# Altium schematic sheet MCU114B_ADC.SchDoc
size 431 x 279 mm; Date: Not shown in title block; ApprovedBy: Not shown in title block; CheckedBy: Not shown in title block; Author: Not shown in title block; CompanyName: Not shown in title block; Engineer: Not shown in title block; Organization: Not shown in title block; Address1: Not shown in title block; Address2: Not shown in title block; Address3: Not shown in title block; Address4: Not shown in title block; DocumentNumber: 4; Revision: Use project parameter SCH_Rev; SheetNumber: 4; SheetTotal: 11; PageSetup: Record=PageOptions¦CenterHorizontal=True¦CenterVertical=True¦PrintScale=1.00¦XCorrection=1.00¦YCorrection=1.00¦PrintKind=0¦BorderSize=5000000¦LeftOffset=0¦BottomOffset=0¦Orientation=2¦PaperLength=1000¦PaperWidth=1000¦Scale=100¦PaperSource=15¦PrintQuality=600¦MediaType=1¦DitherType=10¦PaperKind=Letter¦PrintScaleMode=1
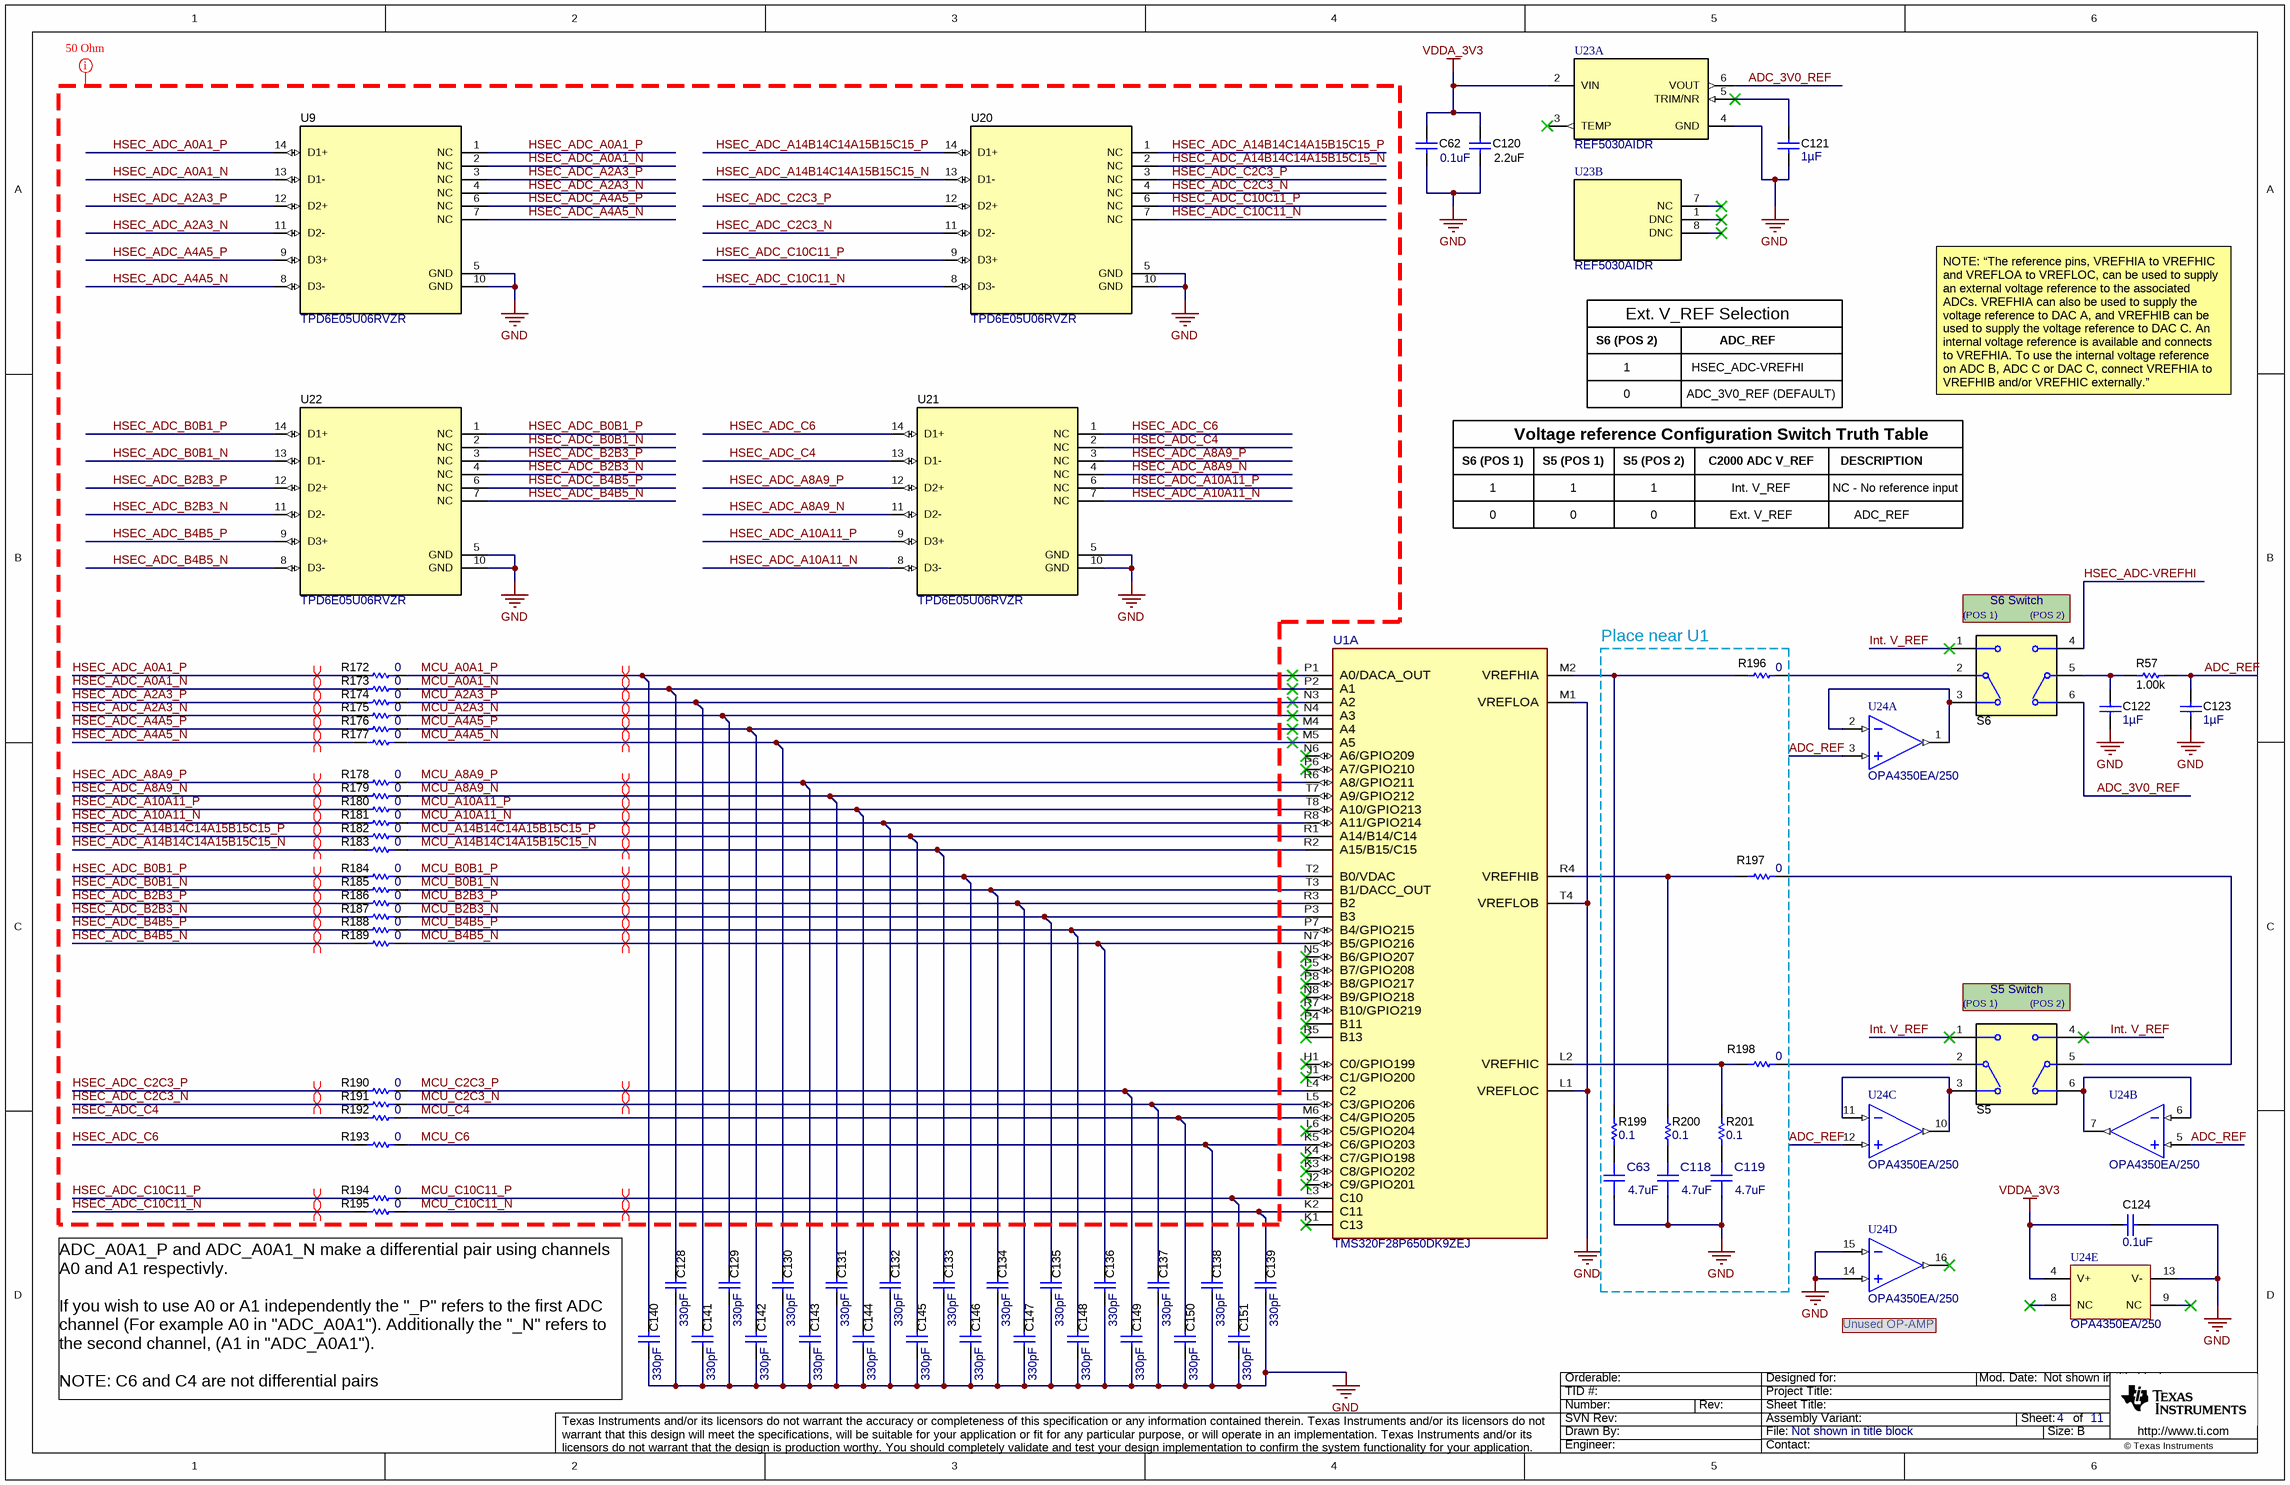
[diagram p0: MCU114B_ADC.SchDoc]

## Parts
C62  Cap_F: 0.1uF  [0603]  (hidden comment: 885012206046)
C63  ValueDisplayed: 4.7uF  [FP-885012106012_0603-MFG]  (hidden comment: 885012106012)
C118  ValueDisplayed: 4.7uF  [FP-885012106012_0603-MFG]  (hidden comment: 885012106012)
C119  ValueDisplayed: 4.7uF  [FP-885012106012_0603-MFG]  (hidden comment: 885012106012)
C120  ValueDisplayed: 2.2uF  [0603]  (hidden comment: 885012106018)
C121  Cap_F: 1µF  [0603]  (hidden comment: 885012206052)
C122  Cap_F: 1µF  [0603]  (hidden comment: 885012206052)
C123  Cap_F: 1µF  [0603]  (hidden comment: 885012206052)
C124  Cap_F: 0.1uF  [0603]  (hidden comment: 885012206046)
C128  ValueDisplayed: 330pF  [0603]  (hidden comment: C0603C331J5GACTU)
C129  ValueDisplayed: 330pF  [0603]  (hidden comment: C0603C331J5GACTU)
C130  ValueDisplayed: 330pF  [0603]  (hidden comment: C0603C331J5GACTU)
C131  ValueDisplayed: 330pF  [0603]  (hidden comment: C0603C331J5GACTU)
C132  ValueDisplayed: 330pF  [0603]  (hidden comment: C0603C331J5GACTU)
C133  ValueDisplayed: 330pF  [0603]  (hidden comment: C0603C331J5GACTU)
C134  ValueDisplayed: 330pF  [0603]  (hidden comment: C0603C331J5GACTU)
C135  ValueDisplayed: 330pF  [0603]  (hidden comment: C0603C331J5GACTU)
C136  ValueDisplayed: 330pF  [0603]  (hidden comment: C0603C331J5GACTU)
C137  ValueDisplayed: 330pF  [0603]  (hidden comment: C0603C331J5GACTU)
C138  ValueDisplayed: 330pF  [0603]  (hidden comment: C0603C331J5GACTU)
C139  ValueDisplayed: 330pF  [0603]  (hidden comment: C0603C331J5GACTU)
C140  ValueDisplayed: 330pF  [0603]  (hidden comment: C0603C331J5GACTU)
C141  ValueDisplayed: 330pF  [0603]  (hidden comment: C0603C331J5GACTU)
C142  ValueDisplayed: 330pF  [0603]  (hidden comment: C0603C331J5GACTU)
C143  ValueDisplayed: 330pF  [0603]  (hidden comment: C0603C331J5GACTU)
C144  ValueDisplayed: 330pF  [0603]  (hidden comment: C0603C331J5GACTU)
C145  ValueDisplayed: 330pF  [0603]  (hidden comment: C0603C331J5GACTU)
C146  ValueDisplayed: 330pF  [0603]  (hidden comment: C0603C331J5GACTU)
C147  ValueDisplayed: 330pF  [0603]  (hidden comment: C0603C331J5GACTU)
C148  ValueDisplayed: 330pF  [0603]  (hidden comment: C0603C331J5GACTU)
C149  ValueDisplayed: 330pF  [0603]  (hidden comment: C0603C331J5GACTU)
C150  ValueDisplayed: 330pF  [0603]  (hidden comment: C0603C331J5GACTU)
C151  ValueDisplayed: 330pF  [0603]  (hidden comment: C0603C331J5GACTU)
R57  ValueDisplayed: 1.00k  [0603]  (hidden comment: RC0603FR-071KL)
R172  ValueDisplayed: 0  [0603]  (hidden comment: ERJ-3GEY0R00V)
R173  ValueDisplayed: 0  [0603]  (hidden comment: ERJ-3GEY0R00V)
R174  ValueDisplayed: 0  [0603]  (hidden comment: ERJ-3GEY0R00V)
R175  ValueDisplayed: 0  [0603]  (hidden comment: ERJ-3GEY0R00V)
R176  ValueDisplayed: 0  [0603]  (hidden comment: ERJ-3GEY0R00V)
R177  ValueDisplayed: 0  [0603]  (hidden comment: ERJ-3GEY0R00V)
R178  ValueDisplayed: 0  [0603]  (hidden comment: ERJ-3GEY0R00V)
R179  ValueDisplayed: 0  [0603]  (hidden comment: ERJ-3GEY0R00V)
R180  ValueDisplayed: 0  [0603]  (hidden comment: ERJ-3GEY0R00V)
R181  ValueDisplayed: 0  [0603]  (hidden comment: ERJ-3GEY0R00V)
R182  ValueDisplayed: 0  [0603]  (hidden comment: ERJ-3GEY0R00V)
R183  ValueDisplayed: 0  [0603]  (hidden comment: ERJ-3GEY0R00V)
R184  ValueDisplayed: 0  [0603]  (hidden comment: ERJ-3GEY0R00V)
R185  ValueDisplayed: 0  [0603]  (hidden comment: ERJ-3GEY0R00V)
R186  ValueDisplayed: 0  [0603]  (hidden comment: ERJ-3GEY0R00V)
R187  ValueDisplayed: 0  [0603]  (hidden comment: ERJ-3GEY0R00V)
R188  ValueDisplayed: 0  [0603]  (hidden comment: ERJ-3GEY0R00V)
R189  ValueDisplayed: 0  [0603]  (hidden comment: ERJ-3GEY0R00V)
R190  ValueDisplayed: 0  [0603]  (hidden comment: ERJ-3GEY0R00V)
R191  ValueDisplayed: 0  [0603]  (hidden comment: ERJ-3GEY0R00V)
R192  ValueDisplayed: 0  [0603]  (hidden comment: ERJ-3GEY0R00V)
R193  ValueDisplayed: 0  [0603]  (hidden comment: ERJ-3GEY0R00V)
R194  ValueDisplayed: 0  [0603]  (hidden comment: ERJ-3GEY0R00V)
R195  ValueDisplayed: 0  [0603]  (hidden comment: ERJ-3GEY0R00V)
R196  ValueDisplayed: 0  [0603]  (hidden comment: ERJ-3GEY0R00V)
R197  ValueDisplayed: 0  [0603]  (hidden comment: ERJ-3GEY0R00V)
R198  ValueDisplayed: 0  [0603]  (hidden comment: ERJ-3GEY0R00V)
R199  ValueDisplayed: 0.1  [0402]  (hidden comment: ERJ2BWFR100X)
R200  ValueDisplayed: 0.1  [0402]  (hidden comment: ERJ2BWFR100X)
R201  ValueDisplayed: 0.1  [0402]  (hidden comment: ERJ2BWFR100X)
S5  CAS-D20TA  [SW_CAS-D20TA]  (value not drawn)
S6  CAS-D20TA  [SW_CAS-D20TA]  (value not drawn)
U1  TMS320F28P650DK9ZEJ  [ZEJ0256A-MFG]  (part A of 4)
U9  TPD6E05U06RVZR  [RVZ0014A]
U20  TPD6E05U06RVZR  [RVZ0014A]
U21  TPD6E05U06RVZR  [RVZ0014A]
U22  TPD6E05U06RVZR  [RVZ0014A]
U23  REF5030AIDR  [D0008A_N]  (parts A,B of 2)
U24  OPA4350EA/250  [DBQ0016A_N]  (parts A,B,C,D,E of 5)

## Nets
GND: C62.2 C63.1 C118.1 C119.1 C120.2 C121.2 C122.2 C123.2 C124.2 C128.2 C129.2 C130.2 C131.2 C132.2 C133.2 C134.2 C135.2 C136.2 C137.2 C138.2 C139.2 C140.2 C141.2 C142.2 C143.2 C144.2 C145.2 C146.2 C147.2 C148.2 C149.2 C150.2 C151.2 U1.L1(VREFLOC) U1.M1(VREFLOA) U1.T4(VREFLOB) U9.5(GND) U9.10(GND) U20.5(GND) U20.10(GND) U21.5(GND) U21.10(GND) U22.5(GND) U22.10(GND) U23.4(GND) U24.13(V-) U24.14(IN_D+) U24.15(IN_D-)
VDDA_3V3: C62.1 C120.1 C124.1 U23.2(VIN) U24.4(V+)
ADC_3V0_REF: S6.6 U23.6(VOUT)
ADC_REF: C123.1 R57.2 U24.3(IN_A+) U24.5(IN_B+) U24.12(IN_C+)
HSEC_ADC-VREFHI: S6.4
HSEC_ADC_A0A1_N: R173.2 U9.2(NC) U9.13(D1-)
HSEC_ADC_A0A1_P: R172.2 U9.1(NC) U9.14(D1+)
HSEC_ADC_A2A3_N: R175.2 U9.4(NC) U9.11(D2-)
HSEC_ADC_A2A3_P: R174.2 U9.3(NC) U9.12(D2+)
HSEC_ADC_A4A5_N: R177.2 U9.7(NC) U9.8(D3-)
HSEC_ADC_A4A5_P: R176.2 U9.6(NC) U9.9(D3+)
HSEC_ADC_A8A9_N: R179.2 U21.4(NC) U21.11(D2-)
HSEC_ADC_A8A9_P: R178.2 U21.3(NC) U21.12(D2+)
HSEC_ADC_A10A11_N: R181.2 U21.7(NC) U21.8(D3-)
HSEC_ADC_A10A11_P: R180.2 U21.6(NC) U21.9(D3+)
HSEC_ADC_A14B14C14A15B15C15_N: R183.2 U20.2(NC) U20.13(D1-)
HSEC_ADC_A14B14C14A15B15C15_P: R182.2 U20.1(NC) U20.14(D1+)
HSEC_ADC_B0B1_N: R185.2 U22.2(NC) U22.13(D1-)
HSEC_ADC_B0B1_P: R184.2 U22.1(NC) U22.14(D1+)
HSEC_ADC_B2B3_N: R187.2 U22.4(NC) U22.11(D2-)
HSEC_ADC_B2B3_P: R186.2 U22.3(NC) U22.12(D2+)
HSEC_ADC_B4B5_N: R189.2 U22.7(NC) U22.8(D3-)
HSEC_ADC_B4B5_P: R188.2 U22.6(NC) U22.9(D3+)
HSEC_ADC_C2C3_N: R191.2 U20.4(NC) U20.11(D2-)
HSEC_ADC_C2C3_P: R190.2 U20.3(NC) U20.12(D2+)
HSEC_ADC_C4: R192.2 U21.2(NC) U21.13(D1-)
HSEC_ADC_C6: R193.2 U21.1(NC) U21.14(D1+)
HSEC_ADC_C10C11_N: R195.2 U20.7(NC) U20.8(D3-)
HSEC_ADC_C10C11_P: R194.2 U20.6(NC) U20.9(D3+)
Int. V_REF: S5.1 S5.4 S6.1
MCU_A0A1_N: C128.1 R173.1 U1.P2(A1)
MCU_A0A1_P: C140.1 R172.1 U1.P1(A0/DACA_OUT)
MCU_A2A3_N: C129.1 R175.1 U1.N4(A3)
MCU_A2A3_P: C141.1 R174.1 U1.N3(A2)
MCU_A4A5_N: C130.1 R177.1 U1.M5(A5)
MCU_A4A5_P: C142.1 R176.1 U1.M4(A4)
MCU_A8A9_N: C131.1 R179.1 U1.T7(A9/GPIO212)
MCU_A8A9_P: C143.1 R178.1 U1.R6(A8/GPIO211)
MCU_A10A11_N: C132.1 R181.1 U1.R8(A11/GPIO214)
MCU_A10A11_P: C144.1 R180.1 U1.T8(A10/GPIO213)
MCU_A14B14C14A15B15C15_N: C133.1 R183.1 U1.R2(A15/B15/C15)
MCU_A14B14C14A15B15C15_P: C145.1 R182.1 U1.R1(A14/B14/C14)
MCU_B0B1_N: C134.1 R185.1 U1.T3(B1/DACC_OUT)
MCU_B0B1_P: C146.1 R184.1 U1.T2(B0/VDAC)
MCU_B2B3_N: C135.1 R187.1 U1.P3(B3)
MCU_B2B3_P: C147.1 R186.1 U1.R3(B2)
MCU_B4B5_N: C136.1 R189.1 U1.N7(B5/GPIO216)
MCU_B4B5_P: C148.1 R188.1 U1.P7(B4/GPIO215)
MCU_C2C3_N: C137.1 R191.1 U1.L5(C3/GPIO206)
MCU_C2C3_P: C149.1 R190.1 U1.L4(C2)
MCU_C4: C150.1 R192.1 U1.M6(C4/GPIO205)
MCU_C6: C138.1 R193.1 U1.K5(C6/GPIO203)
MCU_C10C11_N: C139.1 R195.1 U1.K2(C11)
MCU_C10C11_P: C151.1 R194.1 U1.L3(C10)
NetC63_2: C63.2 R199.1
NetC118_2: C118.2 R200.1
NetC119_2: C119.2 R201.1
NetC121_1: C121.1 U23.5(TRIM/NR)
NetC122_1: C122.1 R57.1 S6.5(C)
NetR196_1: R196.1 S6.2(C)
NetR196_2: R196.2 R199.2 U1.M2(VREFHIA)
NetR197_1: R197.1 S5.5(C)
NetR197_2: R197.2 R200.2 U1.R4(VREFHIB)
NetR198_1: R198.1 S5.2(C)
NetR198_2: R198.2 R201.2 U1.L2(VREFHIC)
NetS5_3: S5.3 U24.10(OUT_C) U24.11(IN_C-)
NetS5_6: S5.6 U24.6(IN_B-) U24.7(OUT_B)
NetS6_3: S6.3 U24.1(OUT_A) U24.2(IN_A-)

Not connected (* = marked no-connect by the designer): U1 H1(C0/GPIO199)* J1(C1/GPIO200)* J2(C9/GPIO201)* K1(C13)* K3(C8/GPIO202)* K4(C7/GPIO198)* L6(C5/GPIO204)* N5(B6/GPIO207)* N6(A6/GPIO209)* N8(B9/GPIO218)* P4(B11)* P5(B7/GPIO208)* P6(A7/GPIO210)* P8(B8/GPIO217)* R5(B13)* R7(B10/GPIO219)*; U23 1(DNC)* 3(TEMP)* 7(NC)* 8(DNC)*; U24 8(NC)* 9(NC)* 16(OUT_D)*

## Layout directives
differential pair: HSEC_ADC_A0A1_N, HSEC_ADC_A0A1_P, HSEC_ADC_A2A3_N, HSEC_ADC_A2A3_P, HSEC_ADC_A4A5_N, HSEC_ADC_A4A5_P, HSEC_ADC_A8A9_N, HSEC_ADC_A8A9_P, HSEC_ADC_A10A11_N, HSEC_ADC_A10A11_P, HSEC_ADC_A14B14C14A15B15C15_N, HSEC_ADC_A14B14C14A15B15C15_P, HSEC_ADC_B0B1_N, HSEC_ADC_B0B1_P, HSEC_ADC_B2B3_N, HSEC_ADC_B2B3_P, HSEC_ADC_B4B5_N, HSEC_ADC_B4B5_P, HSEC_ADC_C2C3_N, HSEC_ADC_C2C3_P, HSEC_ADC_C10C11_N, HSEC_ADC_C10C11_P, MCU_A0A1_N, MCU_A0A1_P, MCU_A2A3_N, MCU_A2A3_P, MCU_A4A5_N, MCU_A4A5_P, MCU_A8A9_N, MCU_A8A9_P, MCU_A10A11_N, MCU_A10A11_P, MCU_A14B14C14A15B15C15_N, MCU_A14B14C14A15B15C15_P, MCU_B0B1_N, MCU_B0B1_P, MCU_B2B3_N, MCU_B2B3_P, MCU_B4B5_N, MCU_B4B5_P, MCU_C2C3_N, MCU_C2C3_P, MCU_C10C11_N, MCU_C10C11_P
50 Ohm Impedance: Undefined: GND, HSEC_ADC_A0A1_N, HSEC_ADC_A0A1_P, HSEC_ADC_A2A3_N, HSEC_ADC_A2A3_P, HSEC_ADC_A4A5_N, HSEC_ADC_A4A5_P, HSEC_ADC_A8A9_N, HSEC_ADC_A8A9_P, HSEC_ADC_A10A11_N, HSEC_ADC_A10A11_P, HSEC_ADC_A14B14C14A15B15C15_N, HSEC_ADC_A14B14C14A15B15C15_P, HSEC_ADC_B0B1_N, HSEC_ADC_B0B1_P, HSEC_ADC_B2B3_N, HSEC_ADC_B2B3_P, HSEC_ADC_B4B5_N, HSEC_ADC_B4B5_P, HSEC_ADC_C2C3_N, HSEC_ADC_C2C3_P, HSEC_ADC_C4, HSEC_ADC_C6, HSEC_ADC_C10C11_N, HSEC_ADC_C10C11_P, MCU_A0A1_N, MCU_A0A1_P, MCU_A2A3_N, MCU_A2A3_P, MCU_A4A5_N, MCU_A4A5_P, MCU_A8A9_N, MCU_A8A9_P, MCU_A10A11_N, MCU_A10A11_P, MCU_A14B14C14A15B15C15_N, MCU_A14B14C14A15B15C15_P, MCU_B0B1_N, MCU_B0B1_P, MCU_B2B3_N, MCU_B2B3_P, MCU_B4B5_N, MCU_B4B5_P, MCU_C2C3_N, MCU_C2C3_P, MCU_C4, MCU_C6, MCU_C10C11_N, MCU_C10C11_P

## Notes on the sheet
- S6 (POS 2)
- 1
- Ext. V_REF Selection
- HSEC_ADC-VREFHI
- ADC_REF
- 0
- Voltage reference Configuration Switch Truth Table
- ADC_3V0_REF (DEFAULT)
- NOTE: “The reference pins, VREFHIA to VREFHIC and VREFLOA to VREFLOC, can be used to supply an external voltage reference to the associated ADCs. VREFHIA can also be used to supply the voltage reference to DAC A, and VREFHIB can be used to supply the voltage reference to DAC C. An internal voltage reference is available and connects to VREFHIA. To use the internal voltage reference on ADC B, ADC C or DAC C, connect VREFHIA to VREFHIB and/or VREFHIC externally.”
- S6 (POS 1)
- S5 (POS 1)
- S5 (POS 2)
- Int. V_REF
- C2000 ADC V_REF
- DESCRIPTION
- NC - No reference input
- Ext. V_REF
- Place near U1
- (near S6) (POS 1)
- (near S6) S6 Switch
- (near S6) (POS 2)
- (near S5) (POS 1)
- (near S5) S5 Switch
- (near S5) (POS 2)
- (near U24) Unused OP-AMP
- ADC_A0A1_P and ADC_A0A1_N make a differential pair using channels A0 and A1 respectivly.
  If you wish to use A0 or A1 independently the "_P" refers to the first ADC channel (For example A0 in "ADC_A0A1"). Additionally the "_N" refers to the second channel, (A1 in "ADC_A0A1").
  NOTE: C6 and C4 are not differential pairs

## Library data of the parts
C62 C124 = CMP-0006829-4: CAP, CERM, 0.1 uF, 16 V, +/- 10%, X7R, 0603; Manufacturer: Wurth Elektronik; TaMin_C: -55°C; Polarized: N; SizeAreaWB_mm2: 4.68; Value1: Unknown; U/M: EA; Value: 0.1uF; TaMax_C: 125°C; SizeZ_mm: 1; SizeX_mm: 1.6; SizeY_mm: 0.8; Value2: 16V; SizeArea_mm2: 1.28; AEC Category: Q200
C63 C118 C119 = CMP-0097305-1: 4.7 µF ±20% 10V Ceramic Capacitor X5R 0603 (1608 Metric); Manufacturer: Wurth Electronics; Cap_F: 4.7µF; Value: 4.7µF; AEC Qualified: No; SizeZ_mm: 0.87mm; TempCo: 15%
C120 = CMP-0006825-5: CAP, CERM, 2.2 uF, 16 V, +/- 20%, X5R, 0603; Manufacturer: Wurth Elektronik; TaMin_C: -55°C; Polarized: N; SizeAreaWB_mm2: 4.68; Value1: Unknown; U/M: EA; Value: 2.2uF; TaMax_C: 85°C; SizeZ_mm: 1; SizeX_mm: 1.6; SizeY_mm: 0.8; Value2: 16V; SizeArea_mm2: 1.28; Cap_F: 2.2µF; AEC Category: Q200
C121-C123 = CMP-0006831-4: CAP, CERM, 1 uF, 16 V, +/- 10%, X7R, 0603; Manufacturer: Wurth Elektronik; TaMin_C: -55°C; Polarized: N; SizeAreaWB_mm2: 4.68; Value1: Unknown; U/M: EA; Value: 1uF; TaMax_C: 125°C; SizeZ_mm: 1; SizeX_mm: 1.6; SizeY_mm: 0.8; Value2: 16V; SizeArea_mm2: 1.28; AEC Category: Q200
C128-C151 = CMP-0006920-4: CAP, CERM, 330 pF, 50 V, +/- 5%, C0G/NP0, 0603; Manufacturer: Kemet; TaMin_C: -55°C; Polarized: N; SizeAreaWB_mm2: 4.68; Value1: Unknown; U/M: EA; Value: 330pF; TaMax_C: 125°C; SizeZ_mm: 1; SizeX_mm: 1.6; SizeY_mm: 0.8; Value2: 50V; SizeArea_mm2: 1.28; AEC Category: Q200
R57 = CMP-0022895-5: RES, 1.00 k, 1%, 0.1 W, 0603; Manufacturer: Yageo; Power_W: 100mW; TempCo: 100 ppm/C; Value_Code: 1k00; Value: 1.00k; EIA_Code: E96; Res_ohm: 1k; SizeX_mm: 1.6; SizeY_mm: 0.8; SizeZ_mm: 1; Value2: 0.1W; SizeArea_mm2: 1.28; AEC Qualified: N; VDC_V: 75V; AEC Category: Q200; SizeAreaWB_mm2: 4.68
R172-R198 = CMP-0025874-4: RES, 0, 5%, 0.1 W, AEC-Q200 Grade 0, 0603; Manufacturer: Panasonic; Power_W: 100mW; TempCo: 600 ppm/C; Value_Code: 0000; Value: 0; EIA_Code: E24; SizeX_mm: 1.6; SizeY_mm: 0.8; SizeZ_mm: 1; Value2: 0.1W; SizeArea_mm2: 1.28; AEC Qualified: Y; VDC_V: 50V; AEC Category: Q200; SizeAreaWB_mm2: 4.68
R199-R201 = CMP-0078660-1: RES, 0.1, 1%, 0.25 W, 0402; Manufacturer: Panasonic; Power_W: 250mW; TempCo: 300 ppm/C; Value_Code: R100; Value: 0.1; EIA_Code: E96; SizeX_mm: 1; SizeY_mm: 0.5; SizeZ_mm: 0.6; Value2: 0.25W; AEC Qualified: N; AEC Category: Q200
S5 S6 = CMP-0002233-1: Switch, Dual SPDT,  2 Pos, 0.1A, 6VDC, SMD; Manufacturer: Copal Electronics; CurrentRating_mA: 100A; SwitchFunction: On-On; VDC_V: 6V; PositionCount: 2
U1 = CMP-0096042-2: Real-Time Microcontroller NFBGA256; Manufacturer: Texas Instruments; AEC Category: Q200; Core Architecture: C28x; Data Bus Width: 32bits; Number Of Ethernet Channels: 1; Number Of Cores: 2; CompType: IC; Number Of I/Os: 159; Interface: I2C,SPI,UART,CAN,USB,LIN,SCI,Ethernet,Other; Number Of Pwm Channels: 36; AEC Qualified: No; Number Of Timers/Counters: 6; Standoff Height: 0.35mm; Number Of Spi Channels: 4; SizeZ_mm: 1.4mm; Number Of Adc Channels: 40; Ram Size: 248KBytes; Frequency_Fixed: 200MHz; Memory Size: 1.28MBytes; Number Of A/D Converters: 3; Memory Type: FLASH
U9 U20-U22 = CMP-0073614-1: 6-Channel Ultra-Low-Capacitance IEC ESD Protection Diodes, RVZ0014A (USON-14); Alternate Manufacturer: Texas Instruments; Green_Lifecycle: Active; SizeAreaWB_mm2: 10.575; Green_REACh: Passed; U/M: EA; SizeZ_mm: 0.55; SizeX_mm: 1.35; SizeY_mm: 3.5; SizeArea_mm2: 4.725; CompType: IC
U23 = CMP-0032592-1: Low Noise, Very Low Drift, Precision Voltage Reference, -40 to 125 degC, 8-pin SOIC (D), Green (RoHS & no Sb/Br); Manufacturer: Texas Instruments; Iq(Max)(uA): 1000; SubFamily: Series Voltage Reference; Temp Coeff(Max)(ppm/ degree C): 3; VI(Min)(V): 3.2; Rating: Catalog; Initial Accuracy @ 25/deg C(%): 0.05; VI(Max)(V): 18; Iout/Iz(Max)(mA): 10
U24 = CMP-0041147-1: High-Speed, Single-Supply, Rail-to-Rail Operational Amplifier MicroAmplifier(TM) Series, 2.7 to 5.5 V, -55 to 150 degC, 16-pin SOP (DBQ16), Green (RoHS & no Sb/Br); Manufacturer: Texas Instruments; Number of Channels: 4; Vio (25C)(Max)(mV): 0.5; Total Supply Voltage(Min)(+5V is 5, +/-5V is 10): 2.7; Slew Rate(Typ)(V/us): 22; Total Supply Voltage(Max)(+5V is 5, +/-5V is 10): 5.5; Iq per channel(Max)(mA): 7.5; Vn at 1kHz(Typ)(nV/rtHz): 18; Sub Family: Low Input Bias Current Amp (<=10pA), Low Offset Voltage Amplifier (<=500uV), Low Supply Voltage Amplifier (<=2.7V), Precision Amplifier; IIB(Max)(pA): 10; CMRR(Min)(dB): 66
